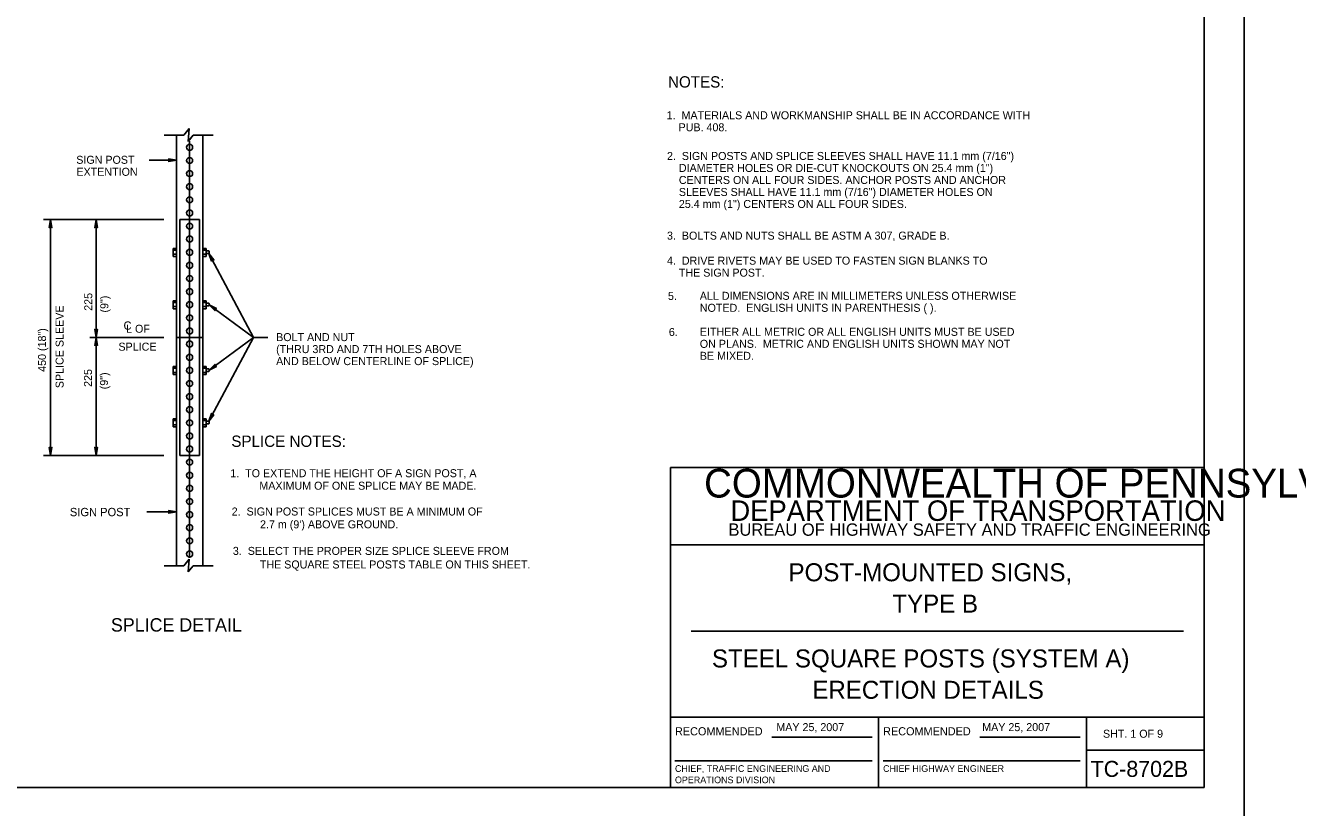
# Model space of a CAD drawing. Extents: x 644358 to 648627, y 294594 to 295782.
# Drawn here: x 644742.6 to 645219.3, y 295195.1 to 295488.4 of the extents above; entities that cross this region are included whole.
import ezdxf

# ---------------------------------------------------------------- set-up
doc = ezdxf.new("R2010")
doc.units = 0
for name, color, linetype in [('1', 7, 'Continuous'), ('2', 7, 'Continuous'), ('3', 7, 'Continuous'), ('4', 7, 'Continuous'), ('PLT-BNDY', 7, 'Continuous')]:
    doc.layers.add(name, color=color, linetype=linetype)

# ---------------------------------------------------------------- blocks, each defined once
blk = doc.blocks.new('RARROW')
at = {"layer": '3'}
blk.add_lwpolyline([(-2.2695, 0.285), (-2.184875, 0.12075), (0, 0), (-2.2695, 0.285), (-2.38575, 0.384625), (0, 0), (-2.183125, -0.108), (-2.262875, -0.2705), (0, 0), (-2.38575, -0.379125), (-2.262875, -0.2705)], dxfattribs=at)

msp = doc.modelspace()

# ---------------------------------------------------------------- linework, layer by layer
at = {"layer": '1'}
for p, q in [((645184.31, 295202.63), (645184.31, 295766.63)), ((644984.31, 295202.63), (644984.31, 295322.63)), ((644984.31, 295322.63), (645184.31, 295322.63)), ((645184.31, 295293.63), (644984.31, 295293.63)), ((644992.06, 295261.31), (645176.56, 295261.31)), ((644984.31, 295229), (645184.31, 295229)), ((645062.31, 295229), (645062.31, 295202.63)), ((645140.19, 295202.63), (645140.19, 295229)), ((645022.24, 295221.57), (645059.87, 295221.57)), ((645100.24, 295221.57), (645137.87, 295221.57)), ((644985.99, 295212.68), (645059.87, 295212.68)), ((645063.99, 295212.68), (645137.87, 295212.68)), ((645140.19, 295216.63), (645184.31, 295216.63)), ((645184.31, 295202.63), (644398.31, 295202.63)), ((644398.31, 295202.63), (644984.31, 295202.63))]:
    msp.add_line(p, q, dxfattribs=at)
at = {"layer": '2'}
for p, q in [((644794.56, 295447.25), (644801.94, 295447.25)), ((644799.19, 295447.25), (644799.19, 295371.38)), ((644801.94, 295447.25), (644803.94, 295449.75)), ((644803.94, 295449.75), (644803.56, 295444.88)), ((644803.56, 295444.88), (644805.44, 295447.25)), ((644812.94, 295447.25), (644805.44, 295447.25)), ((644809.06, 295371.38), (644809.06, 295447.25)), ((644804.06, 295445), (644804.06, 295288.75)), ((644804.06, 295442.63), (644804.06, 295442.63)), ((644804.06, 295437.75), (644804.06, 295437.75)), ((644804.06, 295432.88), (644804.06, 295432.88)), ((644804.06, 295427.88), (644804.06, 295427.88)), ((644804.06, 295423), (644804.06, 295423)), ((644804.06, 295418.13), (644804.06, 295418.13)), ((644800.44, 295415.59), (644807.81, 295415.59)), ((644800.44, 295415.59), (644800.44, 295327.13)), ((644804.06, 295413.13), (644804.06, 295413.13)), ((644807.81, 295415.59), (644807.81, 295327.13)), ((644804.06, 295408.25), (644804.06, 295408.25)), ((644797.94, 295404.75), (644797.94, 295401.75)), ((644797.94, 295404.75), (644799.19, 295404.75)), ((644797.94, 295404.13), (644799.19, 295404.13)), ((644797.94, 295402.63), (644799.19, 295402.63)), ((644804.06, 295403.38), (644804.06, 295403.38)), ((644810.31, 295404.75), (644809.06, 295404.75)), ((644810.31, 295404.13), (644809.06, 295404.13)), ((644810.31, 295402.63), (644809.06, 295402.63)), ((644810.31, 295404.75), (644810.31, 295401.75)), ((644810.31, 295403.88), (644811.31, 295403.88)), ((644810.31, 295402.88), (644811.31, 295402.88)), ((644811.44, 295403.63), (644811.31, 295403.88)), ((644811.44, 295403), (644811.31, 295402.88)), ((644811.44, 295403), (644811.44, 295403.63)), ((644797.94, 295401.75), (644799.19, 295401.75)), ((644804.06, 295398.38), (644804.06, 295398.38)), ((644810.31, 295401.75), (644809.06, 295401.75)), ((644804.06, 295393.5), (644804.06, 295393.5)), ((644804.06, 295388.5), (644804.06, 295388.5)), ((644797.94, 295385.08), (644797.94, 295382.08)), ((644797.94, 295385.08), (644799.19, 295385.08)), ((644797.94, 295384.46), (644799.19, 295384.46)), ((644804.06, 295383.75), (644804.06, 295383.75)), ((644810.31, 295385.08), (644809.06, 295385.08)), ((644810.31, 295384.46), (644809.06, 295384.46)), ((644810.31, 295385.08), (644810.31, 295382.08)), ((644810.31, 295384.21), (644811.31, 295384.21)), ((644811.44, 295383.96), (644811.31, 295384.21)), ((644811.44, 295383.33), (644811.44, 295383.96)), ((644797.94, 295382.96), (644799.19, 295382.96)), ((644797.94, 295382.08), (644799.19, 295382.08)), ((644810.31, 295382.96), (644809.06, 295382.96)), ((644810.31, 295382.08), (644809.06, 295382.08)), ((644810.31, 295383.21), (644811.31, 295383.21)), ((644811.44, 295383.33), (644811.31, 295383.21)), ((644804.06, 295378.75), (644804.06, 295378.75)), ((644799.19, 295371.38), (644799.19, 295285.75)), ((644799.19, 295371.38), (644809.06, 295371.38)), ((644804.06, 295373.75), (644804.06, 295373.75)), ((644809.06, 295285.75), (644809.06, 295371.38)), ((644804.06, 295369), (644804.06, 295369)), ((644797.94, 295357.54), (644797.94, 295360.54)), ((644797.94, 295360.54), (644799.19, 295360.54)), ((644797.94, 295359.92), (644799.19, 295359.92)), ((644804.06, 295364), (644804.06, 295364)), ((644810.31, 295360.54), (644809.06, 295360.54)), ((644810.31, 295359.92), (644809.06, 295359.92)), ((644810.31, 295357.54), (644810.31, 295360.54)), ((644797.94, 295358.29), (644799.19, 295358.29)), ((644797.94, 295357.54), (644799.19, 295357.54)), ((644804.06, 295359), (644804.06, 295359)), ((644810.31, 295358.29), (644809.06, 295358.29)), ((644810.31, 295357.54), (644809.06, 295357.54)), ((644810.31, 295359.67), (644811.31, 295359.67)), ((644810.31, 295358.67), (644811.31, 295358.67)), ((644811.44, 295359.42), (644811.31, 295359.67)), ((644811.44, 295358.79), (644811.31, 295358.67)), ((644811.44, 295359.42), (644811.44, 295358.79)), ((644804.06, 295354.13), (644804.06, 295354.13)), ((644804.06, 295349.25), (644804.06, 295349.25)), ((644797.94, 295337.88), (644797.94, 295340.88)), ((644797.94, 295340.88), (644799.19, 295340.88)), ((644804.06, 295344.25), (644804.06, 295344.25)), ((644810.31, 295340.88), (644809.06, 295340.88)), ((644810.31, 295337.88), (644810.31, 295340.88)), ((644797.94, 295340.25), (644799.19, 295340.25)), ((644797.94, 295338.63), (644799.19, 295338.63)), ((644797.94, 295337.88), (644799.19, 295337.88)), ((644804.06, 295339.38), (644804.06, 295339.38)), ((644810.31, 295340.25), (644809.06, 295340.25)), ((644810.31, 295338.63), (644809.06, 295338.63)), ((644810.31, 295337.88), (644809.06, 295337.88)), ((644810.31, 295340), (644811.31, 295340)), ((644810.31, 295339), (644811.31, 295339)), ((644811.44, 295339.75), (644811.31, 295340)), ((644811.44, 295339.13), (644811.31, 295339)), ((644811.44, 295339.75), (644811.44, 295339.13)), ((644804.06, 295334.5), (644804.06, 295334.5)), ((644800.44, 295327.13), (644807.81, 295327.13)), ((644804.06, 295329.63), (644804.06, 295329.63)), ((644804.06, 295324.63), (644804.06, 295324.63)), ((644804.06, 295319.63), (644804.06, 295319.63)), ((644804.06, 295314.88), (644804.06, 295314.88)), ((644804.06, 295309.88), (644804.06, 295309.88)), ((644804.06, 295304.88), (644804.06, 295304.88)), ((644804.06, 295300), (644804.06, 295300)), ((644804.06, 295295.13), (644804.06, 295295.13)), ((644801.94, 295285.75), (644803.94, 295288.25)), ((644803.94, 295288.25), (644803.56, 295283.5)), ((644804.06, 295290.25), (644804.06, 295290.25)), ((644794.56, 295285.75), (644801.94, 295285.75)), ((644803.56, 295283.5), (644805.44, 295285.75)), ((644812.94, 295285.75), (644805.44, 295285.75))]:
    msp.add_line(p, q, dxfattribs=at)
for centre in [(644804.11, 295442.7), (644804.11, 295437.75), (644804.11, 295432.83), (644804.11, 295427.91), (644804.11, 295423), (644804.11, 295418.08), (644804.11, 295413.13), (644804.11, 295408.28), (644804.11, 295403.33), (644804.11, 295398.41), (644804.11, 295393.5), (644804.11, 295388.58), (644804.11, 295383.66), (644804.11, 295378.74), (644804.11, 295373.83), (644804.11, 295368.91), (644804.11, 295363.96), (644804.11, 295359.04), (644804.11, 295354.12), (644804.11, 295349.21), (644804.11, 295344.29), (644804.11, 295339.37), (644804.11, 295334.46), (644804.11, 295329.54), (644804.11, 295324.62), (644804.11, 295319.71), (644804.11, 295314.79), (644804.11, 295309.87), (644804.11, 295304.95), (644804.11, 295300.04), (644804.11, 295295.12), (644804.11, 295290.2)]:
    msp.add_circle(centre, 1.12, dxfattribs=at)
at = {"layer": '4'}
for p, q in [((644828.1, 295371.38), (644811.31, 295402.88)), ((644828.1, 295371.38), (644811.44, 295383.65)), ((644804.06, 295371.38), (644809.06, 295371.38)), ((644828.1, 295371.38), (644811.31, 295340)), ((644828.1, 295371.38), (644811.44, 295359.11))]:
    msp.add_line(p, q, dxfattribs=at)
for points in [[(644788.98, 295437.82), (644799.19, 295437.82)], [(644749.36, 295415.59), (644794.44, 295415.59)], [(644751.99, 295415.59), (644751.99, 295327.13)], [(644769.06, 295415.59), (644769.06, 295371.38)], [(644766.69, 295371.38), (644794.44, 295371.38)], [(644769.06, 295327.13), (644769.06, 295371.38)], [(644828.1, 295371.38), (644833.36, 295371.38)], [(644749.36, 295327.13), (644794.44, 295327.13)], [(644788.11, 295306), (644799.19, 295306)]]:
    msp.add_lwpolyline(points, dxfattribs=at)
at = {"layer": 'PLT-BNDY'}
for points in [[(644358.31, 295781.63), (645199.31, 295781.63), (645199.31, 295187.63), (644358.31, 295187.63)], [(645199.31, 295781.63), (646040.31, 295781.63), (646040.31, 295187.63), (645199.31, 295187.63)]]:
    msp.add_lwpolyline(points, close=True, dxfattribs=at)

# ---------------------------------------------------------------- block references
at = {"layer": '2', "xscale": 1.2574347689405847, "yscale": 1.3092961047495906}
for p in [(644799.19, 295437.82), (644799.19, 295306)]:
    msp.add_blockref('RARROW', p, dxfattribs=at)
at = {"layer": '2'}
for p, xscale, yscale, rotation in [((644751.99, 295415.59), 1.2574347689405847, 1.3092961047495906, 89.99999999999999), ((644769.06, 295415.59), 1.2574347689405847, 1.3092961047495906, 89.99999999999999), ((644811.31, 295402.88), 1.257434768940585, 1.3092961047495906, 118.6809314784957), ((644811.44, 295383.65), 1.257434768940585, 1.3092961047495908, 144.24684404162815), ((644769.06, 295371.38), 1.2574347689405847, 1.3092961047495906, -90.00000000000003), ((644769.06, 295371.38), 1.2574347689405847, 1.3092961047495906, 89.99999999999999), ((644811.44, 295359.11), 1.2574347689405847, 1.3092961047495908, -143.77483896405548), ((644811.31, 295340), 1.2574347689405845, 1.3092961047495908, -117.96802497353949), ((644751.99, 295327.13), 1.2574347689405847, 1.3092961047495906, -90.00000000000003), ((644769.06, 295327.13), 1.2574347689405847, 1.3092961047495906, -90.00000000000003)]:
    msp.add_blockref('RARROW', p, dxfattribs=dict(at, xscale=xscale, yscale=yscale, rotation=rotation))

# ---------------------------------------------------------------- texts
at = {"layer": '1'}
for s, height, p in [('COMMONWEALTH OF PENNSYLVANIA', 10.7828, (644996.9, 295311.36)), ('DEPARTMENT OF TRANSPORTATION', 7.6837, (645006.76, 295302.61)), ('BUREAU OF HIGHWAY SAFETY AND TRAFFIC ENGINEERING', 4.6253, (645006.04, 295297.04)), ('POST-MOUNTED SIGNS,', 6.75, (645028.54, 295279.97)), ('TYPE B', 6.75, (645067.45, 295268.22)), ('STEEL SQUARE POSTS (SYSTEM A)', 6.75, (644999.84, 295247.66)), ('ERECTION DETAILS', 6.75, (645037.47, 295235.91)), ('RECOMMENDED', 3.048, (644985.99, 295222.2)), ('RECOMMENDED', 3.048, (645063.99, 295222.2)), ('SHT. 1 OF 9', 3, (645146.39, 295221.31)), ('TC-8702B', 6, (645141.77, 295206.63)), ('CHIEF, TRAFFIC ENGINEERING AND', 2.5, (644985.99, 295208.51)), ('CHIEF HIGHWAY ENGINEER', 2.5, (645063.99, 295208.51)), ('OPERATIONS DIVISION', 2.5, (644985.99, 295204.26))]:
    msp.add_text(s, height=height, dxfattribs=at).set_placement(p)
at = {"layer": '2'}
for s, height, p in [('SPLICE DETAIL', 5, (644774.6, 295261.12)), ('MAY 25, 2007', 3, (645023.98, 295223.79)), ('MAY 25, 2007', 3, (645101.14, 295223.79))]:
    msp.add_text(s, height=height, dxfattribs=at).set_placement(p)
at = {"layer": '4'}
for s, height, p in [('NOTES:', 4.25, (644983.39, 295465.08)), ('1.  MATERIALS AND WORKMANSHIP SHALL BE IN ACCORDANCE WITH ', 3, (644982.87, 295453.19)), ('    PUB. 408.', 3, (644982.87, 295448.69)), ('2.  SIGN POSTS AND SPLICE SLEEVES SHALL HAVE 11.1 mm (7/16")', 3, (644982.99, 295437.94)), ('SIGN POST', 3, (644761.61, 295436.5)), ('    DIAMETER HOLES OR DIE-CUT KNOCKOUTS ON 25.4 mm (1")', 3, (644982.99, 295433.44)), ('EXTENTION', 3, (644761.67, 295432)), ('    CENTERS ON ALL FOUR SIDES. ANCHOR POSTS AND ANCHOR ', 3, (644982.99, 295428.94)), ('    SLEEVES SHALL HAVE 11.1 mm (7/16") DIAMETER HOLES ON', 3, (644982.99, 295424.44)), ('    25.4 mm (1") CENTERS ON ALL FOUR SIDES.', 3, (644982.99, 295419.94)), ('3.  BOLTS AND NUTS SHALL BE ASTM A 307, GRADE B.', 3, (644982.99, 295408.07)), ('4.  DRIVE RIVETS MAY BE USED TO FASTEN SIGN BLANKS TO', 3, (644982.99, 295398.69)), ('    THE SIGN POST.', 3, (644982.99, 295394.19)), ('5.', 3, (644983.37, 295385.45)), ('ALL DIMENSIONS ARE IN MILLIMETERS UNLESS OTHERWISE', 3, (644995.3, 295385.5)), ('NOTED.  ENGLISH UNITS IN PARENTHESIS ( ).', 3, (644995.3, 295381)), ('C', 3.11, (644779.33, 295374.29)), ('L OF', 3, (644780.29, 295373.15)), ('6.', 3, (644983.7, 295371.94)), ('EITHER ALL METRIC OR ALL ENGLISH UNITS MUST BE USED', 3, (644995.3, 295372)), ('SPLICE', 3, (644777.42, 295366.43)), ('BOLT AND NUT', 3, (644836.52, 295370.02)), ('ON PLANS.  METRIC AND ENGLISH UNITS SHOWN MAY NOT ', 3, (644995.3, 295367.5)), ('(THRU 3RD AND 7TH HOLES ABOVE', 3, (644836.52, 295365.52)), ('BE MIXED.', 3, (644995.3, 295363)), ('AND BELOW CENTERLINE OF SPLICE)', 3, (644836.52, 295361.02)), ('SPLICE NOTES:', 4.25, (644819.73, 295330.36)), ('1.  TO EXTEND THE HEIGHT OF A SIGN POST, A', 3, (644819.34, 295318.99)), (' MAXIMUM OF ONE SPLICE MAY BE MADE.', 3, (644829.12, 295314.3)), ('SIGN POST', 3.115, (644759.22, 295304.37)), ('2.  SIGN POST SPLICES MUST BE A MINIMUM OF', 3, (644819.86, 295304.63)), (" 2.7 m (9') ABOVE GROUND.", 3, (644829.37, 295299.82)), ('3.  SELECT THE PROPER SIZE SPLICE SLEEVE FROM', 3, (644820.31, 295289.86)), (' THE SQUARE STEEL POSTS TABLE ON THIS SHEET.', 3, (644829.29, 295284.77))]:
    msp.add_text(s, height=height, dxfattribs=at).set_placement(p)
for s, p in [('225', (644767.62, 295381.39)), ('(9")', (644773.63, 295380.73)), ('SPLICE SLEEVE', (644756.87, 295352.38)), ('450 (18")', (644750.28, 295358.49)), ('225', (644767.5, 295352.85)), ('(9")', (644773.51, 295351.96))]:
    msp.add_text(s, height=3, rotation=90, dxfattribs=at).set_placement(p)

doc.saveas('drawing.dxf')
